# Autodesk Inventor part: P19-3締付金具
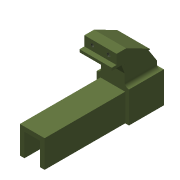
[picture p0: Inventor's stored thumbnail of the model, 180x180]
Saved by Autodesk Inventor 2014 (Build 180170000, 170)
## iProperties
Created: 2008-07
Part Number: P19-3締付金具
Document SubType Name: Modeling
Designer: y-shimohigashi
Density: 1 g/cm^3
Stock Number: P19-3締付金具
Material: 一般
Appearance: Olive Drab
Author: y-shimohigashi
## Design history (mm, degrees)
sketch "スケッチ3"
  geometry: L1 (43, 22)-(43, 80); L2 (43, 80)-(38, 80); L3 (38, 80)-(38, 93); L4 (38, 93)-(16, 127); L5 (16, 127)-(-27, 149); L6 (-27, 149)-(-45, 149); L7 (-45, 149)-(-45, 131); L8 (-45, 131)-(-54, 131); L9 (-54, 131)-(-54, 126); L10 (-54, 126)-(-44, 126); L11 (-44, 126)-(-31, 126); L12 (-31, 126)-(-22, 102); L13 (-22, 102)-(-22, 22); L14 (-22, 22)-(43, 22); 1 further point
  constraints: 28 end point, 6 parallel, 1 horizontal, 1 perpendicular, 1 vertical
  dimensions: "d4" = 58 distance of L1.start L1.end; "d5" = 13 distance of L2.end L3.end; "d6" = 34 vertical distance of L3.end L4.end; "d7" = 22 vertical distance of L4.end L5.end; "d8" = 5 distance of L1.end L2.end; "d9" = 22 horizontal distance of L3.end L4.end; "d10" = 43 horizontal distance of L4.end L5.end; "d11" = 18 distance of L5.end L6.end; "d12" = 9 distance of L7.end L8.end; "d13" = 18 distance of L6.end L7.end; "d14" = 5 distance of L8.end L9.end; "d15" = 10 distance of L9.end L10.end; "d16" = 24 vertical distance of L11.end L12.end; "d17" = 80 distance of L12.end L13.end; "d18" = 65 distance between parallel lines of L1 L13; "d19" = 13 distance of L10.end L11.end; "d66" = 43 distance from line of L1 point (0, 0); "d67" = 22 distance from line of point (0, 0) L14
extrude "押し出し2" new body sketch "スケッチ3" stored distance "d20" = 60; taper "d21" = 0 deg
sketch "スケッチ4"
  geometry: L1 (0, 0)-(60, 0) reference; L2 (60, 0)-(52, 0); L3 (52, 0)-(52, -45); L4 (52, -45)-(60, -45); L5 (60, -45)-(60, 0); L6 (0, 0)-(8, 0); L7 (8, 0)-(8, -45); L8 (8, -45)-(0, -45); L9 (0, -45)-(0, 0)
  constraints: 16 end point, 4 parallel, 2 collinear, 2 horizontal, 2 perpendicular
  dimensions: "d22" = 8 distance of L3.end L4.end; "d23" = 45 distance of L4.end L1.end
extrude "押し出し3" cut sketch "スケッチ4" stored distance "d24" = 60; taper "d25" = 0 deg
sketch "スケッチ9"
  geometry: L1 (-60, 58)-(-60, 0) reference; L2 (-60, 0)-(0, 0) reference; L3 (0, 0)-(0, 58) reference; L4 (0, 58)-(-60, 58) reference; L5 (-53, 51)-(-53, 0); L6 (-7, 0)-(-7, 51); L7 (-7, 51)-(-53, 51); L8 (-53, 0)-(-44.5, 0); L9 (-44.5, 42.5)-(-15.5, 42.5); L10 (-15.5, 42.5)-(-15.5, 0); L11 (-44.5, 42.5)-(-44.5, 0); L12 (-15.5, 0)-(-7, 0)
  constraints: 16 end point, 4 point on line, 2 parallel, 2 perpendicular, 1 collinear
  dimensions: "d68" = 7 distance between parallel lines of L7 L4; "d69" = 7 distance between parallel lines of L5 L1 (= d68); "d70" = 7 distance between parallel lines of L3 L6 (= d68); "d71" = 8.5 distance between parallel lines of L9 L7; "d72" = 8.5 distance between parallel lines of L11 L5 (= d71)
extrude "押し出し6" join sketch "スケッチ9" distance "d74" = 215; taper "d75" = 0 deg
sketch "スケッチ10"
  geometry: L1 (60, 0)-(0, 0) reference; 2 further points
  constraints: 1 midpoint, 1 vertical alignment
  dimensions: "d85" = 25.5 distance from line of L1 point (30, -25.5)
hole "穴4" sketch "スケッチ10" at (30, -25.5) diameter "d76" = 16; stored, may be unused: countersink angle "d80" = 90 deg, drill point angle "d82" = 118 deg; dims "d77" = 6, "d78" = 36, "d79" = 15, "d81" = 8
feature "ねじ1" dims "d83" = 10, "d84" = 0
sketch "スケッチ11"
  geometry: L1 (30, -152.4)-(30, 25.4) reference; L2 (60, -18)-(60, 0) reference; 3 further points
  constraints: 2 horizontal alignment, 1 midpoint, 1 symmetric about line
  dimensions: "d88" = 30 distance of point (45, -9) point (15, -9)
hole "穴5" sketch "スケッチ11" at (15, -9), (45, -9) diameter "d89" = 6.647; stored, may be unused: countersink angle "d93" = 90 deg, drill point angle "d95" = 118 deg; dims "d90" = 6, "d91" = 36, "d92" = 15, "d94" = 8
fillet "フィレット4" dims "d96" = 8
node "ソリッド1"
node "ソリッド ボディ"
node "サーフェス ボディ"
node "投影ループ2"
